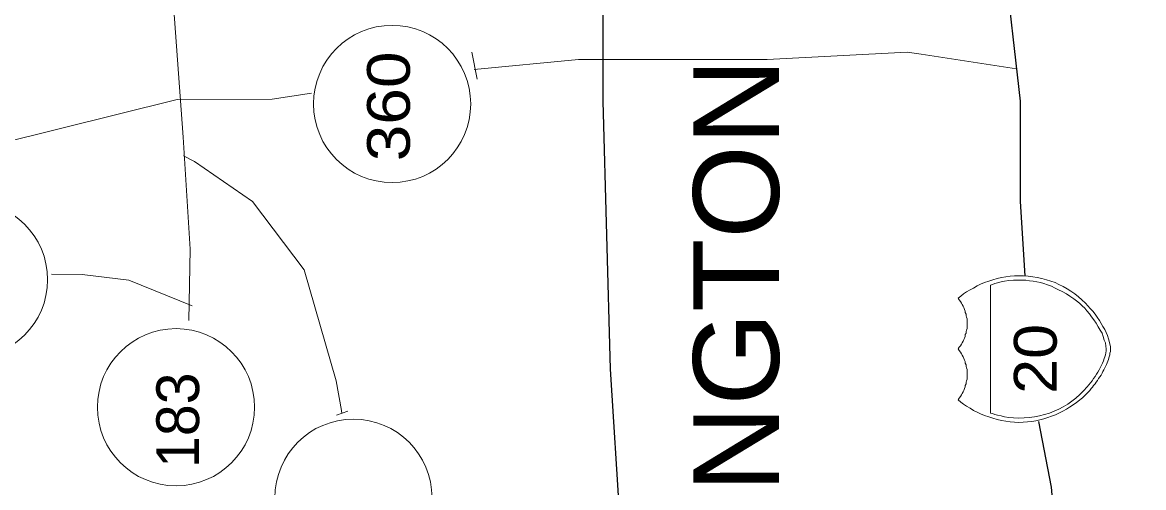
# Model space of a CAD drawing. Extents: x 2363323 to 2367082, y 6956018 to 6980837.
# Drawn here: x 2365927 to 2366060.5, y 6980677.3 to 6980732.7 of the extents above; entities that cross this region are included whole.
import ezdxf

# ---------------------------------------------------------------- set-up
doc = ezdxf.new("R2010")
doc.units = 0
doc.header["$LTSCALE"] = 4.1
doc.layers.add('62', color=7, linetype='Continuous', lineweight=13)
doc.layers.add('63', color=7, linetype='Continuous', lineweight=13)

msp = doc.modelspace()

# ---------------------------------------------------------------- linework, layer by layer
at = {"layer": '62'}
for p, q in [((2365981.134, 6980725.983), (2365980.504, 6980729.18)), ((2366032.391, 6980729.18), (2366034.056, 6980728.977)), ((2366034.056, 6980728.977), (2366045.399, 6980727.198)), ((2365993.194, 6980728.323), (2365980.796, 6980727.13)), ((2365945.378, 6980723.576), (2365956.719, 6980723.577)), ((2365956.719, 6980723.577), (2365961.398, 6980724.318)), ((2365947.449, 6980716.172), (2365946.144, 6980716.848)), ((2365946.952, 6980705.732), (2365946.795, 6980697.204)), ((2365934.08, 6980702.694), (2365930.434, 6980702.762)), ((2365964.322, 6980690.048), (2365964.976, 6980686.491)), ((2365964.39, 6980685.951), (2365965.74, 6980686.402)), ((2365965.022, 6980686.154), (2365964.976, 6980686.491))]:
    msp.add_line(p, q, dxfattribs=at)
for points in [[(2365946.952, 6980705.732), (2365946.12, 6980719.074), (2365944.412, 6980742.408), (2365945.356, 6980763.81), (2365946.075, 6980778.052), (2365946.279, 6980796.078), (2365943.802, 6980806.407), (2365936.646, 6980818.286), (2365929.917, 6980831.541), (2365928.768, 6980835.546)], [(2365993.194, 6980728.323), (2366002.914, 6980728.322), (2366015.674, 6980728.323), (2366032.391, 6980729.18)], [(2365945.378, 6980723.576), (2365917.071, 6980716.532), (2365897.424, 6980705.979)], [(2365964.322, 6980690.048), (2365960.544, 6980703.279), (2365954.356, 6980711.403), (2365947.449, 6980716.172)], [(2365947.2, 6980698.982), (2365939.618, 6980702.019), (2365934.08, 6980702.694)], [(2366038.919, 6980694.57), (2366039.032, 6980694.772), (2366039.122, 6980694.954), (2366039.19, 6980695.132), (2366039.279, 6980695.336), (2366039.302, 6980695.539), (2366039.392, 6980695.695), (2366039.416, 6980695.899), (2366039.46, 6980696.078), (2366039.504, 6980696.28), (2366039.526, 6980696.462), (2366039.526, 6980696.664), (2366039.526, 6980696.866), (2366039.526, 6980697.046), (2366039.526, 6980697.226), (2366039.504, 6980697.428), (2366039.459, 6980697.609), (2366039.416, 6980697.79), (2366039.393, 6980697.992), (2366039.303, 6980698.172), (2366039.28, 6980698.352), (2366039.189, 6980698.554), (2366039.122, 6980698.756), (2366039.032, 6980698.938), (2366038.92, 6980699.116), (2366038.83, 6980699.296), (2366038.716, 6980699.476), (2366038.58, 6980699.702), (2366038.469, 6980699.88), (2366038.763, 6980700.129), (2366039.099, 6980700.4), (2366039.458, 6980700.646), (2366039.864, 6980700.872), (2366040.269, 6980701.096), (2366040.698, 6980701.344), (2366041.124, 6980701.546), (2366041.598, 6980701.749), (2366042.092, 6980701.908), (2366042.586, 6980702.064), (2366043.104, 6980702.222), (2366043.623, 6980702.334), (2366044.14, 6980702.426), (2366044.636, 6980702.49), (2366045.152, 6980702.538), (2366045.669, 6980702.56), (2366046.232, 6980702.536), (2366046.796, 6980702.492), (2366047.356, 6980702.426), (2366047.874, 6980702.356), (2366048.414, 6980702.244), (2366048.956, 6980702.064), (2366049.472, 6980701.906), (2366049.99, 6980701.749), (2366050.462, 6980701.524), (2366050.956, 6980701.256), (2366051.429, 6980701.006), (2366051.88, 6980700.714), (2366052.352, 6980700.399), (2366052.779, 6980700.062), (2366053.184, 6980699.702), (2366053.612, 6980699.296), (2366053.906, 6980698.982), (2366054.196, 6980698.666), (2366054.49, 6980698.329), (2366054.76, 6980697.992), (2366055.006, 6980697.609), (2366055.276, 6980697.226), (2366055.502, 6980696.866), (2366055.704, 6980696.506), (2366055.906, 6980696.148), (2366056.086, 6980695.786), (2366056.244, 6980695.426), (2366056.356, 6980695.042), (2366056.448, 6980694.75), (2366056.514, 6980694.412), (2366056.582, 6980694.12), (2366056.582, 6980693.848)], [(2366056.582, 6980693.848), (2366056.582, 6980693.67), (2366056.582, 6980693.512), (2366056.536, 6980693.312), (2366056.514, 6980693.152), (2366056.469, 6980692.995), (2366056.403, 6980692.791), (2366056.356, 6980692.59), (2366056.289, 6980692.388), (2366056.199, 6980692.185), (2366056.109, 6980691.982), (2366056.02, 6980691.758), (2366055.929, 6980691.578), (2366055.816, 6980691.352), (2366055.704, 6980691.148), (2366055.592, 6980690.948), (2366055.48, 6980690.722), (2366055.322, 6980690.52), (2366055.186, 6980690.294), (2366055.052, 6980690.07), (2366054.896, 6980689.888), (2366054.76, 6980689.686), (2366054.58, 6980689.485), (2366054.446, 6980689.26), (2366054.286, 6980689.102), (2366054.129, 6980688.9), (2366053.972, 6980688.718), (2366053.792, 6980688.518), (2366053.613, 6980688.362), (2366053.433, 6980688.18), (2366053.274, 6980688.022), (2366053.116, 6980687.889), (2366052.914, 6980687.728), (2366052.554, 6980687.438), (2366052.15, 6980687.168), (2366051.723, 6980686.899), (2366051.339, 6980686.671), (2366050.912, 6980686.424), (2366050.462, 6980686.2), (2366050.036, 6980685.996), (2366049.584, 6980685.816), (2366049.136, 6980685.658), (2366048.662, 6980685.501), (2366048.19, 6980685.388), (2366047.716, 6980685.276), (2366047.223, 6980685.186), (2366046.728, 6980685.141), (2366046.188, 6980685.094), (2366045.669, 6980685.074), (2366045.152, 6980685.118), (2366044.634, 6980685.164), (2366044.14, 6980685.21), (2366043.622, 6980685.321), (2366043.104, 6980685.435), (2366042.588, 6980685.568), (2366042.092, 6980685.726), (2366041.598, 6980685.884), (2366041.124, 6980686.086), (2366040.698, 6980686.287), (2366040.269, 6980686.514), (2366039.864, 6980686.762), (2366039.459, 6980687.008), (2366039.099, 6980687.235), (2366038.763, 6980687.505), (2366038.47, 6980687.754), (2366038.582, 6980687.955), (2366038.716, 6980688.159), (2366038.83, 6980688.36), (2366038.919, 6980688.519), (2366039.033, 6980688.72), (2366039.123, 6980688.9), (2366039.189, 6980689.102), (2366039.279, 6980689.305), (2366039.303, 6980689.485), (2366039.392, 6980689.665), (2366039.414, 6980689.869), (2366039.459, 6980690.048), (2366039.504, 6980690.248), (2366039.526, 6980690.43), (2366039.526, 6980690.612), (2366039.528, 6980690.835), (2366039.526, 6980690.992), (2366039.528, 6980691.195), (2366039.506, 6980691.376), (2366039.459, 6980691.578), (2366039.416, 6980691.759), (2366039.392, 6980691.939), (2366039.303, 6980692.142), (2366039.279, 6980692.342), (2366039.189, 6980692.5), (2366039.123, 6980692.704), (2366039.033, 6980692.905), (2366038.919, 6980693.109), (2366038.829, 6980693.265), (2366038.718, 6980693.468), (2366038.583, 6980693.648), (2366038.469, 6980693.852), (2366038.582, 6980694.03), (2366038.718, 6980694.186), (2366038.829, 6980694.392), (2366038.919, 6980694.57)]]:
    msp.add_lwpolyline(points, dxfattribs=at)
at = {"layer": '62', "lineweight": 25}
for points in [[(2365988.154, 6980835.546), (2365989.437, 6980822.404), (2365992.248, 6980802.402), (2365995.06, 6980778.345), (2365996.118, 6980752.4), (2365996.118, 6980723.35), (2365996.997, 6980691.422), (2365998.12, 6980673.24)], [(2366060.542, 6980835.548), (2366053.23, 6980822.404), (2366049.539, 6980805.483), (2366044.949, 6980788.336), (2366043.892, 6980764.532), (2366043.014, 6980750.487), (2366043.892, 6980740.474), (2366045.825, 6980723.35), (2366045.826, 6980711.446), (2366046.412, 6980702.514)], [(2366048.01, 6980685.208), (2366049.539, 6980677.378), (2366050.418, 6980667.388), (2366051.476, 6980653.346), (2366051.474, 6980643.356), (2366052.352, 6980636.2), (2366055.164, 6980631.206), (2366057.122, 6980621.192), (2366056.064, 6980607.15), (2366055.164, 6980594.301), (2366054.309, 6980580.237), (2366057.123, 6980558.096), (2366054.309, 6980537.146), (2366050.416, 6980520.246), (2366044.949, 6980510.235), (2366031.738, 6980507.152), (2366018.51, 6980507.151), (2366011.984, 6980505.261), (2366002.646, 6980510.235)]]:
    msp.add_lwpolyline(points, dxfattribs=at)
at = {"layer": '62'}
msp.add_lwpolyline([(2366042.318, 6980701.434), (2366042.316, 6980686.2), (2366042.543, 6980686.131), (2366042.812, 6980686.018), (2366043.126, 6980685.928), (2366043.554, 6980685.862), (2366043.982, 6980685.75), (2366044.499, 6980685.66), (2366045.062, 6980685.614), (2366045.67, 6980685.591), (2366046.3, 6980685.614), (2366046.929, 6980685.658), (2366047.559, 6980685.748), (2366048.144, 6980685.861), (2366048.752, 6980686.018), (2366049.314, 6980686.198), (2366049.899, 6980686.424), (2366050.439, 6980686.671), (2366050.956, 6980686.944), (2366051.498, 6980687.259), (2366051.993, 6980687.595), (2366052.486, 6980687.979), (2366052.96, 6980688.405), (2366053.386, 6980688.832), (2366053.814, 6980689.305), (2366054.198, 6980689.8), (2366054.422, 6980690.025), (2366054.58, 6980690.294), (2366054.759, 6980690.542), (2366054.916, 6980690.835), (2366055.076, 6980691.06), (2366055.254, 6980691.33), (2366055.389, 6980691.602), (2366055.524, 6980691.892), (2366055.636, 6980692.14), (2366055.749, 6980692.41), (2366055.862, 6980692.682), (2366055.93, 6980692.905), (2366055.996, 6980693.152), (2366056.043, 6980693.378), (2366056.086, 6980693.625), (2366056.088, 6980693.85), (2366056.064, 6980694.165), (2366055.996, 6980694.548), (2366055.862, 6980694.885), (2366055.726, 6980695.312), (2366055.592, 6980695.698), (2366055.366, 6980696.079), (2366055.142, 6980696.484), (2366054.896, 6980696.889), (2366054.624, 6980697.294), (2366054.354, 6980697.656), (2366054.084, 6980698.014), (2366053.793, 6980698.374), (2366053.523, 6980698.712), (2366053.229, 6980698.982), (2366052.96, 6980699.253), (2366052.689, 6980699.454), (2366052.239, 6980699.792), (2366051.766, 6980700.106), (2366051.339, 6980700.399), (2366050.844, 6980700.669), (2366050.416, 6980700.894), (2366049.989, 6980701.096), (2366049.562, 6980701.3), (2366049.112, 6980701.456), (2366048.66, 6980701.614), (2366048.255, 6980701.749), (2366047.806, 6980701.839), (2366047.38, 6980701.906), (2366046.953, 6980701.952), (2366046.524, 6980702.019), (2366046.098, 6980702.019), (2366045.67, 6980702.042), (2366045.062, 6980702.019), (2366044.499, 6980701.976), (2366043.982, 6980701.906), (2366043.554, 6980701.839), (2366043.128, 6980701.726), (2366042.812, 6980701.614), (2366042.543, 6980701.524)], close=True, dxfattribs=at)
for centre in [(2365971.003, 6980723.024), (2365920.587, 6980702.089), (2365945.255, 6980686.887), (2365966.397, 6980676.102)]:
    msp.add_circle(centre, 9.364, dxfattribs=at)
at = {"layer": '63'}
for p, q in [((2365981.134, 6980725.983), (2365980.504, 6980729.18)), ((2366032.391, 6980729.18), (2366034.056, 6980728.977)), ((2366034.056, 6980728.977), (2366045.399, 6980727.198)), ((2365993.194, 6980728.323), (2365980.796, 6980727.13)), ((2365945.378, 6980723.576), (2365956.719, 6980723.577)), ((2365956.719, 6980723.577), (2365961.398, 6980724.318)), ((2365947.449, 6980716.172), (2365946.144, 6980716.848)), ((2365946.952, 6980705.732), (2365946.795, 6980697.204)), ((2365934.08, 6980702.694), (2365930.434, 6980702.762)), ((2365964.322, 6980690.048), (2365964.976, 6980686.491)), ((2365964.39, 6980685.951), (2365965.74, 6980686.402)), ((2365965.022, 6980686.154), (2365964.976, 6980686.491))]:
    msp.add_line(p, q, dxfattribs=at)
for points in [[(2365946.952, 6980705.732), (2365946.12, 6980719.074), (2365944.412, 6980742.408), (2365945.356, 6980763.81), (2365946.075, 6980778.052), (2365946.279, 6980796.078), (2365943.802, 6980806.407), (2365936.646, 6980818.286), (2365929.917, 6980831.541), (2365928.768, 6980835.546)], [(2365993.194, 6980728.323), (2366002.914, 6980728.322), (2366015.674, 6980728.323), (2366032.391, 6980729.18)], [(2365945.378, 6980723.576), (2365917.071, 6980716.532), (2365897.424, 6980705.979)], [(2365964.322, 6980690.048), (2365960.544, 6980703.279), (2365954.356, 6980711.403), (2365947.449, 6980716.172)], [(2365947.2, 6980698.982), (2365939.618, 6980702.019), (2365934.08, 6980702.694)], [(2366038.919, 6980694.57), (2366039.032, 6980694.772), (2366039.122, 6980694.954), (2366039.19, 6980695.132), (2366039.279, 6980695.336), (2366039.302, 6980695.539), (2366039.392, 6980695.695), (2366039.416, 6980695.899), (2366039.46, 6980696.078), (2366039.504, 6980696.28), (2366039.526, 6980696.462), (2366039.526, 6980696.664), (2366039.526, 6980696.866), (2366039.526, 6980697.046), (2366039.526, 6980697.226), (2366039.504, 6980697.428), (2366039.459, 6980697.609), (2366039.416, 6980697.79), (2366039.393, 6980697.992), (2366039.303, 6980698.172), (2366039.28, 6980698.352), (2366039.189, 6980698.554), (2366039.122, 6980698.756), (2366039.032, 6980698.938), (2366038.92, 6980699.116), (2366038.83, 6980699.296), (2366038.716, 6980699.476), (2366038.58, 6980699.702), (2366038.469, 6980699.88), (2366038.763, 6980700.129), (2366039.099, 6980700.4), (2366039.458, 6980700.646), (2366039.864, 6980700.872), (2366040.269, 6980701.096), (2366040.698, 6980701.344), (2366041.124, 6980701.546), (2366041.598, 6980701.749), (2366042.092, 6980701.908), (2366042.586, 6980702.064), (2366043.104, 6980702.222), (2366043.623, 6980702.334), (2366044.14, 6980702.426), (2366044.636, 6980702.49), (2366045.152, 6980702.538), (2366045.669, 6980702.56), (2366046.232, 6980702.536), (2366046.796, 6980702.492), (2366047.356, 6980702.426), (2366047.874, 6980702.356), (2366048.414, 6980702.244), (2366048.956, 6980702.064), (2366049.472, 6980701.906), (2366049.99, 6980701.749), (2366050.462, 6980701.524), (2366050.956, 6980701.256), (2366051.429, 6980701.006), (2366051.88, 6980700.714), (2366052.352, 6980700.399), (2366052.779, 6980700.062), (2366053.184, 6980699.702), (2366053.612, 6980699.296), (2366053.906, 6980698.982), (2366054.196, 6980698.666), (2366054.49, 6980698.329), (2366054.76, 6980697.992), (2366055.006, 6980697.609), (2366055.276, 6980697.226), (2366055.502, 6980696.866), (2366055.704, 6980696.506), (2366055.906, 6980696.148), (2366056.086, 6980695.786), (2366056.244, 6980695.426), (2366056.356, 6980695.042), (2366056.448, 6980694.75), (2366056.514, 6980694.412), (2366056.582, 6980694.12), (2366056.582, 6980693.848)], [(2366056.582, 6980693.848), (2366056.582, 6980693.67), (2366056.582, 6980693.512), (2366056.536, 6980693.312), (2366056.514, 6980693.152), (2366056.469, 6980692.995), (2366056.403, 6980692.791), (2366056.356, 6980692.59), (2366056.289, 6980692.388), (2366056.199, 6980692.185), (2366056.109, 6980691.982), (2366056.02, 6980691.758), (2366055.929, 6980691.578), (2366055.816, 6980691.352), (2366055.704, 6980691.148), (2366055.592, 6980690.948), (2366055.48, 6980690.722), (2366055.322, 6980690.52), (2366055.186, 6980690.294), (2366055.052, 6980690.07), (2366054.896, 6980689.888), (2366054.76, 6980689.686), (2366054.58, 6980689.485), (2366054.446, 6980689.26), (2366054.286, 6980689.102), (2366054.129, 6980688.9), (2366053.972, 6980688.718), (2366053.792, 6980688.518), (2366053.613, 6980688.362), (2366053.433, 6980688.18), (2366053.274, 6980688.022), (2366053.116, 6980687.889), (2366052.914, 6980687.728), (2366052.554, 6980687.438), (2366052.15, 6980687.168), (2366051.723, 6980686.899), (2366051.339, 6980686.671), (2366050.912, 6980686.424), (2366050.462, 6980686.2), (2366050.036, 6980685.996), (2366049.584, 6980685.816), (2366049.136, 6980685.658), (2366048.662, 6980685.501), (2366048.19, 6980685.388), (2366047.716, 6980685.276), (2366047.223, 6980685.186), (2366046.728, 6980685.141), (2366046.188, 6980685.094), (2366045.669, 6980685.074), (2366045.152, 6980685.118), (2366044.634, 6980685.164), (2366044.14, 6980685.21), (2366043.622, 6980685.321), (2366043.104, 6980685.435), (2366042.588, 6980685.568), (2366042.092, 6980685.726), (2366041.598, 6980685.884), (2366041.124, 6980686.086), (2366040.698, 6980686.287), (2366040.269, 6980686.514), (2366039.864, 6980686.762), (2366039.459, 6980687.008), (2366039.099, 6980687.235), (2366038.763, 6980687.505), (2366038.47, 6980687.754), (2366038.582, 6980687.955), (2366038.716, 6980688.159), (2366038.83, 6980688.36), (2366038.919, 6980688.519), (2366039.033, 6980688.72), (2366039.123, 6980688.9), (2366039.189, 6980689.102), (2366039.279, 6980689.305), (2366039.303, 6980689.485), (2366039.392, 6980689.665), (2366039.414, 6980689.869), (2366039.459, 6980690.048), (2366039.504, 6980690.248), (2366039.526, 6980690.43), (2366039.526, 6980690.612), (2366039.528, 6980690.835), (2366039.526, 6980690.992), (2366039.528, 6980691.195), (2366039.506, 6980691.376), (2366039.459, 6980691.578), (2366039.416, 6980691.759), (2366039.392, 6980691.939), (2366039.303, 6980692.142), (2366039.279, 6980692.342), (2366039.189, 6980692.5), (2366039.123, 6980692.704), (2366039.033, 6980692.905), (2366038.919, 6980693.109), (2366038.829, 6980693.265), (2366038.718, 6980693.468), (2366038.583, 6980693.648), (2366038.469, 6980693.852), (2366038.582, 6980694.03), (2366038.718, 6980694.186), (2366038.829, 6980694.392), (2366038.919, 6980694.57)]]:
    msp.add_lwpolyline(points, dxfattribs=at)
at = {"layer": '63', "lineweight": 25}
for points in [[(2365988.154, 6980835.546), (2365989.437, 6980822.404), (2365992.248, 6980802.402), (2365995.06, 6980778.345), (2365996.118, 6980752.4), (2365996.118, 6980723.35), (2365996.997, 6980691.422), (2365998.12, 6980673.24)], [(2366060.542, 6980835.548), (2366053.23, 6980822.404), (2366049.539, 6980805.483), (2366044.949, 6980788.336), (2366043.892, 6980764.532), (2366043.014, 6980750.487), (2366043.892, 6980740.474), (2366045.825, 6980723.35), (2366045.826, 6980711.446), (2366046.412, 6980702.514)], [(2366048.01, 6980685.208), (2366049.539, 6980677.378), (2366050.418, 6980667.388), (2366051.476, 6980653.346), (2366051.474, 6980643.356), (2366052.352, 6980636.2), (2366055.164, 6980631.206), (2366057.122, 6980621.192), (2366056.064, 6980607.15), (2366055.164, 6980594.301), (2366054.309, 6980580.237), (2366057.123, 6980558.096), (2366054.309, 6980537.146), (2366050.416, 6980520.246), (2366044.949, 6980510.235), (2366031.738, 6980507.152), (2366018.51, 6980507.151), (2366011.984, 6980505.261), (2366002.646, 6980510.235)]]:
    msp.add_lwpolyline(points, dxfattribs=at)
at = {"layer": '63'}
msp.add_lwpolyline([(2366042.318, 6980701.434), (2366042.316, 6980686.2), (2366042.543, 6980686.131), (2366042.812, 6980686.018), (2366043.126, 6980685.928), (2366043.554, 6980685.862), (2366043.982, 6980685.75), (2366044.499, 6980685.66), (2366045.062, 6980685.614), (2366045.67, 6980685.591), (2366046.3, 6980685.614), (2366046.929, 6980685.658), (2366047.559, 6980685.748), (2366048.144, 6980685.861), (2366048.752, 6980686.018), (2366049.314, 6980686.198), (2366049.899, 6980686.424), (2366050.439, 6980686.671), (2366050.956, 6980686.944), (2366051.498, 6980687.259), (2366051.993, 6980687.595), (2366052.486, 6980687.979), (2366052.96, 6980688.405), (2366053.386, 6980688.832), (2366053.814, 6980689.305), (2366054.198, 6980689.8), (2366054.422, 6980690.025), (2366054.58, 6980690.294), (2366054.759, 6980690.542), (2366054.916, 6980690.835), (2366055.076, 6980691.06), (2366055.254, 6980691.33), (2366055.389, 6980691.602), (2366055.524, 6980691.892), (2366055.636, 6980692.14), (2366055.749, 6980692.41), (2366055.862, 6980692.682), (2366055.93, 6980692.905), (2366055.996, 6980693.152), (2366056.043, 6980693.378), (2366056.086, 6980693.625), (2366056.088, 6980693.85), (2366056.064, 6980694.165), (2366055.996, 6980694.548), (2366055.862, 6980694.885), (2366055.726, 6980695.312), (2366055.592, 6980695.698), (2366055.366, 6980696.079), (2366055.142, 6980696.484), (2366054.896, 6980696.889), (2366054.624, 6980697.294), (2366054.354, 6980697.656), (2366054.084, 6980698.014), (2366053.793, 6980698.374), (2366053.523, 6980698.712), (2366053.229, 6980698.982), (2366052.96, 6980699.253), (2366052.689, 6980699.454), (2366052.239, 6980699.792), (2366051.766, 6980700.106), (2366051.339, 6980700.399), (2366050.844, 6980700.669), (2366050.416, 6980700.894), (2366049.989, 6980701.096), (2366049.562, 6980701.3), (2366049.112, 6980701.456), (2366048.66, 6980701.614), (2366048.255, 6980701.749), (2366047.806, 6980701.839), (2366047.38, 6980701.906), (2366046.953, 6980701.952), (2366046.524, 6980702.019), (2366046.098, 6980702.019), (2366045.67, 6980702.042), (2366045.062, 6980702.019), (2366044.499, 6980701.976), (2366043.982, 6980701.906), (2366043.554, 6980701.839), (2366043.128, 6980701.726), (2366042.812, 6980701.614), (2366042.543, 6980701.524)], close=True, dxfattribs=at)
for centre in [(2365971.003, 6980723.024), (2365920.587, 6980702.089), (2365945.255, 6980686.887), (2365966.397, 6980676.102)]:
    msp.add_circle(centre, 9.364, dxfattribs=at)

# ---------------------------------------------------------------- texts
at = {"layer": '62'}
for s, height, width, p in [('360', 5.099, 1.15, (2365973.123, 6980716.196)), ('ARLINGTON', 10.21, 1.05, (2366017.091, 6980644.842)), ('20', 5.099, 1.1, (2366050.191, 6980688.474))]:
    msp.add_text(s, height=height, rotation=90, dxfattribs=dict(at, width=width)).set_placement(p)
msp.add_text('183', height=5.099, rotation=90, dxfattribs=at).set_placement((2365948.009, 6980679.651))
at = {"layer": '63'}
for s, height, width, p in [('360', 5.099, 1.15, (2365973.123, 6980716.196)), ('ARLINGTON', 10.21, 1.05, (2366017.091, 6980644.842)), ('20', 5.099, 1.1, (2366050.191, 6980688.474))]:
    msp.add_text(s, height=height, rotation=90, dxfattribs=dict(at, width=width)).set_placement(p)
msp.add_text('183', height=5.099, rotation=90, dxfattribs=at).set_placement((2365948.009, 6980679.651))

doc.saveas('drawing.dxf')
